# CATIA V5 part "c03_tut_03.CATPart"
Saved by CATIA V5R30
Part number: c03tut3
Bounding box of the stored display mesh (mm): x 0 to 0, y -100 to 100, z 0 to 90
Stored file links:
  D:\PROJECTS\CATIA V56R 2020\Resources\c03_catia_v5_6r2020_tut\c03_tut_03.CATPart
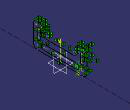
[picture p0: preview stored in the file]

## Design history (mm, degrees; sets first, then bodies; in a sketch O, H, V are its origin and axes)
Body1 (main body)
  Sketch1 on yz-plane, origin (0, 0, 0), H (0, 1, 0), V (0, 0, 1)
    line L1 (0, 0) -> (85, 0)
    line L2 (100, 15) -> (100, 80)
    line L3 (90, 90) -> (70, 90)
    line L4 (60, 80) -> (60, 60)
    line L5 (50, 50) -> (0, 50)
    point P1 (0, 50)
    arc A1 centre (85, 15) radius 15 from (85, 0) to (100, 15) ccw
    point P2 (85, 0)
    point P3 (100, 15)
    arc A2 centre (90, 80) radius 10 from (100, 80) to (90, 90) ccw
    point P5 (100, 80)
    point P6 (90, 90)
    arc A3 centre (70, 80) radius 10 from (70, 90) to (60, 80) ccw
    point P8 (70, 90)
    point P9 (60, 80)
    arc A4 centre (50, 60) radius 10 from (60, 60) to (50, 50) cw
    point P11 (60, 60)
    point P12 (50, 50)
    construction line L6 (80, 40) -> (80, 70)
    line L7 (75, 40) -> (75, 70)
    line L8 (85, 70) -> (85, 40)
    arc A5 centre (80, 70) radius 5 from (75, 70) to (85, 70) cw
    arc A6 centre (80, 40) radius 5 from (85, 40) to (75, 40) cw
    point P16 (75, 40)
    point P17 (75, 70)
    point P18 (85, 70)
    point P19 (85, 40)
    point P20 (0, 0)
    construction line L9 through (0, 0) direction (-1, 0)
    point P21 (0, 50)
    point P22 (-85, 0)
    point P23 (-100, 15)
    point P25 (-100, 80)
    point P26 (-90, 90)
    point P28 (-70, 90)
    point P29 (-60, 80)
    point P31 (-60, 60)
    point P32 (-50, 50)
    construction line L10 (-80, 40) -> (-80, 70)
    point P36 (-75, 40)
    point P37 (-75, 70)
    point P38 (-85, 70)
    point P39 (-85, 40)
    line L11 (-100, 15) -> (-100, 80)
    line L12 (-90, 90) -> (-70, 90)
    line L13 (-60, 80) -> (-60, 60)
    line L14 (-50, 50) -> (0, 50)
    arc A7 centre (-85, 15) radius 15 from (-85, 0) to (-100, 15) cw
    arc A8 centre (-90, 80) radius 10 from (-100, 80) to (-90, 90) cw
    arc A9 centre (-70, 80) radius 10 from (-70, 90) to (-60, 80) cw
    arc A10 centre (-50, 60) radius 10 from (-60, 60) to (-50, 50) ccw
    line L15 (-75, 40) -> (-75, 70)
    line L16 (-85, 70) -> (-85, 40)
    arc A11 centre (-80, 70) radius 5 from (-75, 70) to (-85, 70) ccw
    arc A12 centre (-80, 40) radius 5 from (-85, 40) to (-75, 40) ccw
    line L17 (0, 0) -> (-85, 0)
    construction line L18 (60, 20) -> (-60, 20)
    point P40 (-60, 20)
    line L19 (60, 10) -> (-60, 10)
    line L20 (-60, 30) -> (60, 30)
    arc A13 centre (-60, 20) radius 10 from (-60, 10) to (-60, 30) cw
    arc A14 centre (60, 20) radius 10 from (60, 30) to (60, 10) cw
    radius A1 = 15
    radius A2 = 10
    radius A3 = 10
    radius A4 = 10
    distance L6 L7 = 5
    distance L18 L19 = 10
    horizontal: L1 H, L3 H, L5 H, L18 H
    vertical: L2 V, L4 V, L6 V
    tangency: A1 L1, A1 L2, A2 L2, A2 L3, A3 L3, A3 L4, A4 L4, A4 L5, A5 L7, A6 L7, A5 L8, A6 L8, A13 L19, A14 L19, A13 L20, A14 L20
    symmetry: O P20 V, H L9 V, P1 P21 V, P2 P22 V, P3 P23 V, P5 P25 V, P6 P26 V, P8 P28 V, P9 P29 V, P11 P31 V, P12 P32 V, L6 L10 V, P16 P36 V, P17 P37 V, P18 P38 V, P19 P39 V, L2 L11 V, L3 L12 V, L4 L13 V, L5 L14 V, A1 A7 V, A2 A8 V, A3 A9 V, A4 A10 V, L7 L15 V, L8 L16 V, A5 A11 V, A6 A12 V, L1 L17 V
    coincidence: P40 L13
